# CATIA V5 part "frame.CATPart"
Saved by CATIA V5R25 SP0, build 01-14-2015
Part number: frame
Bounding box of the stored display mesh (mm): x -20 to 20, y -50 to 0, z 0 to 100
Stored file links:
  D:\frame.CATPart
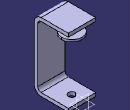
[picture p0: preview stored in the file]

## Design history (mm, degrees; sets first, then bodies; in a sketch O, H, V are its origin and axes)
Body1 (main body)
  Sketch1 on yz-plane, origin (0, 0, 0), H (0, 1, 0), V (0, 0, 1)
    line L1 (0, 0) -> (-50, 0)
    line L2 (-50, 0) -> (-50, 100)
    line L3 (-50, 100) -> (0, 100)
    point P3 (0, 100)
    line L4 (0, 100) -> (0, 95)
    line L5 (0, 95) -> (-45, 95)
    line L6 (-45, 95) -> (-45, 5)
    line L7 (-45, 5) -> (0, 5)
    point P7 (0, 5)
    line L8 (0, 5) -> (0, 0)
    length L2 = 100
    length L4 = 5
    distance L6 L2 = 5
    length L8 = 5
    length L1 = 50
    horizontal: L1 H, L3 H, L5 H, L7 H
    vertical: L2 V, L4 V, L6 V, L8 V
    coincidence: P3 V, P7 V
  Pad1: profile Sketch1, direction (1, 0, 0), length 20, mirrored extent
  Sketch2 on face of Pad1 from Sketch1.L5, origin (0, 0, 95), H (1, 0, 0), V (0, -1, 0)
    circle A1 centre (0, 15) radius 5
    point P1 (0, 15)
    reference intersected line E1 (20, 0) -> (-20, 0) from face of Pad1 from Sketch1.L4
    radius A1 = 5
    distance E1 P1 = 15
    coincidence: P1 V
  Pad2: profile Sketch2, direction (0, 0, -1), length 10
  Sketch3 on end face of Pad2, origin (0, 0, 85), H (1, 0, 0), V (0, -1, 0)
    circle A1 centre (0, 15) radius 15
    point P1 (0, 15)
    reference projected circle E1 centre (0, 15) radius 5 from edge [face of Pad2 from Sketch2.A1 | end face of Pad2]
    radius A1 = 15
    coincidence: P1 V
    concentricity: A1 E1
  Pad3: profile Sketch3, direction (0, 0, -1), length 3
  Sketch4 on face of Pad1 from Sketch1.L1, origin (0, 0, 0), H (1, 0, 0), V (0, -1, 0)
    circle A1 centre (0, 15) radius 5
    point P1 (0, 15)
    radius A1 = 5
    distance H P1 = 15
    coincidence: P1 V
  Pocket1: profile Sketch4, direction (0, 0, 1), through (limit type 6)
  Fillet1: radius 5, on edge [face of Pad1 from Sketch1.L5 | face of Pad1 from Sketch1.L6]; edge [face of Pad1 from Sketch1.L6 | face of Pad1 from Sketch1.L7]
  Fillet2: radius 10, on edge [face of Pad1 from Sketch1.L2 | face of Pad1 from Sketch1.L3]; edge [face of Pad1 from Sketch1.L1 | face of Pad1 from Sketch1.L2]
